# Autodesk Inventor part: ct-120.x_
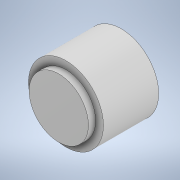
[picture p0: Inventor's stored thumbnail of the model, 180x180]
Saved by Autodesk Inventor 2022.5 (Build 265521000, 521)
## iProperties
Created: 2023-06
Part Number: ct-120.x_
Material: Generic
Document SubType Name: Modeling
Designer: ImaoCorp
Density: 1 g/cm^3
Appearance: Default
Sending System: SOLIDWORKS 2021-2021301
MC: AMD64
MC_MODEL: Intel64 Family 6 Model 60 Stepping 3, GenuineIntel
OS: Windows_NT
FRU: Parasolid Version 32.1, build 255,  1- 1-2021
FORMAT: text
GUISE: transmit
KEY: ct-120
FILE: ct-120.x_t
DATE: Thu Jun 15 15:47:28 2023
Author: ImaoCorp
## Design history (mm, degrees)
feature "Base1"
node "ソリッド1"
